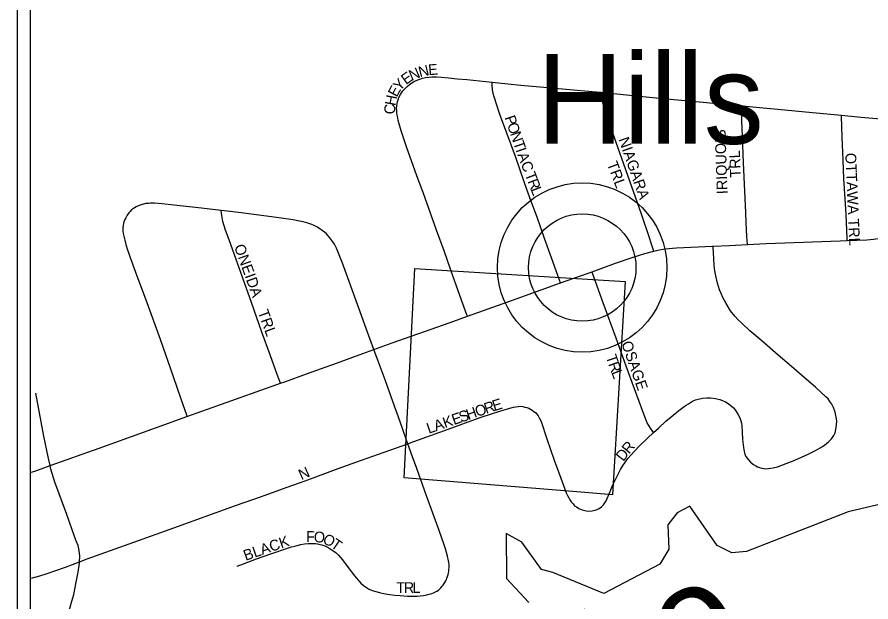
# Model space of a CAD drawing. Extents: x -5.4 to 49.9, y 13.2 to 48.4.
# Drawn here: x 26.266 to 27.015, y 43.012 to 43.526 of the extents above; entities that cross this region are included whole.
import ezdxf

# ---------------------------------------------------------------- set-up
doc = ezdxf.new("R2010")
doc.units = 0
for name, color, linetype in [('GM_X_Corporation', 7, 'Continuous'), ('GM_X_Major_Lake', 7, 'Continuous'), ('GM_X_Major_Lake_Text', 7, 'Continuous'), ('GM_X_Township', 7, 'Continuous'), ('GM_X_Township_Road', 7, 'Continuous'), ('GM_X_Township_Subdivision', 7, 'Continuous'), ('GM_X_Township_Subdivision_Text', 7, 'Continuous'), ('GM_X_Unincorporated', 7, 'Continuous'), ('GM_X_Unincorporated_Location', 7, 'Continuous'), ('GM_X_Unincorporated_Text', 7, 'Continuous')]:
    doc.layers.add(name, color=color, linetype=linetype)

msp = doc.modelspace()

# ---------------------------------------------------------------- linework, layer by layer
at = {"layer": 'GM_X_Corporation'}
msp.add_line((26.26551, 43.78252), (26.26551, 42.05419), dxfattribs=at)
msp.add_lwpolyline([(26.61474, 43.30541), (26.79932, 43.29416), (26.78844, 43.10649), (26.75689, 43.10905), (26.60546, 43.12136), (26.61474, 43.30541)], dxfattribs=at)
at = {"layer": 'GM_X_Major_Lake'}
msp.add_lwpolyline([(27.05104, 43.10483), (26.9954, 43.09164), (26.90591, 43.0568), (26.89299, 43.05556), (26.88025, 43.06191), (26.87364, 43.07155), (26.85638, 43.09659), (26.84525, 43.09076), (26.83706, 43.08032), (26.83771, 43.05868), (26.82984, 43.04557), (26.78074, 43.01971), (26.73603, 43.03815), (26.72586, 43.04103), (26.70858, 43.06493), (26.6951, 43.07244), (26.69535, 43.03297), (26.71498, 43.01205)], dxfattribs=at)
at = {"layer": 'GM_X_Township'}
msp.add_line((26.2771, 45.17828), (26.2771, 40.9761), dxfattribs=at)
at = {"layer": 'GM_X_Township_Road'}
for points in [[(26.90688, 43.32649), (26.92316, 43.32728), (26.94794, 43.32823), (26.98827, 43.32971), (26.99436, 43.32999)], [(26.99436, 43.32999), (27.0118, 43.33078), (27.01744, 43.33118), (27.02367, 43.33221), (27.02492, 43.33258)], [(26.77037, 43.30264), (26.79093, 43.31011), (26.80559, 43.31511), (26.81682, 43.31861), (26.82461, 43.3206)], [(26.82461, 43.3206), (26.82817, 43.3215), (26.83421, 43.3226), (26.84465, 43.32372), (26.87611, 43.32497), (26.87679, 43.325)], [(26.87679, 43.325), (26.89096, 43.32572), (26.90688, 43.32649)], [(26.74281, 43.29278), (26.76702, 43.30142), (26.77037, 43.30264)], [(26.66104, 43.26349), (26.67499, 43.26842), (26.70063, 43.27772), (26.72559, 43.28663), (26.74281, 43.29278)], [(26.5789, 43.23416), (26.59494, 43.23999), (26.64576, 43.25809), (26.66104, 43.26349)], [(26.4967, 43.20464), (26.50049, 43.206), (26.51966, 43.21291), (26.5461, 43.22233), (26.56925, 43.23065), (26.5789, 43.23416)], [(26.41468, 43.17539), (26.44106, 43.18478), (26.4967, 43.20464)], [(26.29447, 43.13221), (26.33759, 43.14753), (26.37642, 43.16151), (26.39434, 43.16814), (26.41468, 43.17539)], [(26.2771, 43.12614), (26.28109, 43.12745), (26.29447, 43.13221)]]:
    msp.add_lwpolyline(points, dxfattribs=at)
at = {"layer": 'GM_X_Township_Subdivision'}
for points in [[(26.66104, 43.26349), (26.66056, 43.26475), (26.65699, 43.27429), (26.65416, 43.28183), (26.64644, 43.3041), (26.6406, 43.32084), (26.63374, 43.33919), (26.62207, 43.37233), (26.61665, 43.38698), (26.60746, 43.41229), (26.60273, 43.4263), (26.60088, 43.43253), (26.60015, 43.43548), (26.5997, 43.43787), (26.59929, 43.44028), (26.59897, 43.44253), (26.5989, 43.4443), (26.59876, 43.44648), (26.59894, 43.44852), (26.59925, 43.4503), (26.59963, 43.45213), (26.60011, 43.45369), (26.60084, 43.45561), (26.6022, 43.45839), (26.60313, 43.45992), (26.60431, 43.46145), (26.60621, 43.46362), (26.60814, 43.46547), (26.6101, 43.46713), (26.61207, 43.46848), (26.61355, 43.46941), (26.61525, 43.47037), (26.61731, 43.47127), (26.61919, 43.47197), (26.62155, 43.47266), (26.62422, 43.4733), (26.62705, 43.47367), (26.62958, 43.47379), (26.63139, 43.47387), (26.63386, 43.47386), (26.63816, 43.47359), (26.6443, 43.47302), (26.65188, 43.47228), (26.66033, 43.47144), (26.68276, 43.46918)], [(26.68276, 43.46918), (26.69649, 43.46779), (26.70793, 43.46671), (26.73125, 43.46466), (26.75084, 43.4629), (26.7706, 43.46113), (26.7783, 43.46036)], [(26.74281, 43.29278), (26.74191, 43.29523), (26.73469, 43.31489), (26.72868, 43.33183), (26.7223, 43.35056), (26.71561, 43.36765), (26.7111, 43.3808), (26.70325, 43.40375), (26.69564, 43.42428), (26.68922, 43.44155), (26.68446, 43.45645), (26.68394, 43.45816), (26.68353, 43.45967), (26.6832, 43.46115), (26.683, 43.46247), (26.68283, 43.46378), (26.68281, 43.46572), (26.68276, 43.46918)], [(26.7783, 43.46036), (26.78923, 43.45927), (26.82087, 43.45612), (26.84215, 43.454), (26.86793, 43.45157), (26.89395, 43.44911), (26.90269, 43.44835)], [(26.82461, 43.3206), (26.82265, 43.32677), (26.82059, 43.3333), (26.81367, 43.35329), (26.79992, 43.39217), (26.79152, 43.41633), (26.78388, 43.43829), (26.78082, 43.44762), (26.77982, 43.45138), (26.77884, 43.4554), (26.77848, 43.45843), (26.7783, 43.46036)], [(26.90688, 43.32649), (26.90643, 43.33365), (26.90583, 43.3459), (26.9054, 43.35472), (26.90347, 43.39839), (26.90243, 43.4218), (26.90182, 43.43528), (26.90193, 43.44031), (26.90213, 43.44354), (26.90239, 43.44639), (26.90269, 43.44835)], [(26.90269, 43.44835), (26.91746, 43.44706), (26.93349, 43.44541), (26.96381, 43.44258), (26.98934, 43.44019)], [(26.98934, 43.44019), (27.00649, 43.43859), (27.03764, 43.43588), (27.06877, 43.43298), (27.07594, 43.43232), (27.08162, 43.43152), (27.08606, 43.43062), (27.08894, 43.42996), (27.09214, 43.42897), (27.09502, 43.42774), (27.09749, 43.42651), (27.10003, 43.42519), (27.10283, 43.42346), (27.10764, 43.41985), (27.1164, 43.41327), (27.13392, 43.39922)], [(26.99436, 43.32999), (26.99429, 43.33171), (26.99344, 43.35317), (26.99154, 43.38454), (26.99073, 43.40067), (26.99001, 43.42075), (26.98936, 43.43899), (26.98934, 43.44019)], [(26.44479, 43.35632), (26.42746, 43.35835), (26.40868, 43.36064), (26.39812, 43.36176), (26.39254, 43.36235), (26.3895, 43.36259), (26.38605, 43.36277), (26.38275, 43.36287), (26.38087, 43.36267), (26.37852, 43.36246), (26.37541, 43.36176), (26.37281, 43.36094), (26.36994, 43.35962), (26.3678, 43.35831), (26.36607, 43.35708), (26.36467, 43.35568), (26.36361, 43.35437), (26.36213, 43.35231), (26.3609, 43.35007), (26.36016, 43.34853), (26.35938, 43.34649), (26.359, 43.34489), (26.35863, 43.34333), (26.35835, 43.34187), (26.35827, 43.34039), (26.35835, 43.33842), (26.35868, 43.33612), (26.35917, 43.33381), (26.35999, 43.33044), (26.36106, 43.32656), (26.36252, 43.32175), (26.36352, 43.31869), (26.36482, 43.31525), (26.36948, 43.3023), (26.37935, 43.27567), (26.39105, 43.24332), (26.40253, 43.21045), (26.40933, 43.19095), (26.41425, 43.17676), (26.41468, 43.17539)], [(26.5789, 43.23416), (26.57562, 43.24299), (26.57089, 43.25602), (26.56562, 43.27059), (26.56106, 43.28337), (26.55483, 43.30056), (26.55118, 43.31019), (26.54782, 43.31894), (26.54585, 43.32337), (26.54413, 43.32675), (26.5419, 43.33012), (26.53999, 43.33248), (26.53853, 43.33422), (26.53714, 43.33579), (26.53541, 43.33727), (26.53338, 43.33898), (26.53179, 43.34014), (26.52923, 43.34178), (26.52686, 43.34294), (26.52421, 43.34421), (26.52094, 43.34533), (26.51684, 43.3464), (26.51215, 43.34738), (26.5078, 43.3482), (26.4954, 43.3501), (26.48009, 43.35215), (26.46239, 43.35439), (26.44997, 43.35572), (26.44479, 43.35632)], [(26.4967, 43.20464), (26.49402, 43.21236), (26.48779, 43.22945), (26.48049, 43.24951), (26.47126, 43.27561), (26.46232, 43.30094), (26.45161, 43.33076), (26.44863, 43.33904), (26.44608, 43.34674), (26.44522, 43.35217), (26.44479, 43.35632)], [(26.82439, 43.1613), (26.82862, 43.16521), (26.83509, 43.17124), (26.83979, 43.1752), (26.84333, 43.17817), (26.84777, 43.18154), (26.8512, 43.18415), (26.85302, 43.18529), (26.85515, 43.18661), (26.85674, 43.18767), (26.85859, 43.18875), (26.86114, 43.18998), (26.86345, 43.19064), (26.86739, 43.19154), (26.87109, 43.19187), (26.8743, 43.19187), (26.8789, 43.19113), (26.88244, 43.19024), (26.88498, 43.18933), (26.88741, 43.18818), (26.88901, 43.18727), (26.89097, 43.18608), (26.89229, 43.18497), (26.89446, 43.18295), (26.896, 43.18119), (26.89698, 43.17987), (26.89845, 43.17732), (26.90013, 43.1742), (26.90109, 43.17144), (26.90159, 43.16952), (26.90181, 43.1673), (26.90225, 43.16178), (26.90262, 43.15508), (26.9034, 43.14822), (26.90397, 43.14461), (26.90463, 43.14231), (26.90553, 43.14033), (26.90652, 43.13885), (26.90767, 43.13745), (26.90965, 43.13524), (26.91203, 43.13333), (26.91416, 43.13195), (26.91556, 43.13121), (26.91745, 43.13055), (26.91943, 43.13006), (26.92296, 43.12948), (26.92534, 43.12956), (26.92946, 43.13014), (26.93307, 43.13129), (26.94853, 43.13701), (26.9602, 43.14239), (26.96663, 43.14563), (26.97055, 43.14773), (26.97442, 43.15028), (26.97812, 43.15307), (26.98058, 43.15578), (26.98272, 43.15858), (26.98371, 43.16113), (26.98453, 43.164), (26.98511, 43.16812), (26.98527, 43.17116), (26.98506, 43.17331), (26.98455, 43.1764), (26.98388, 43.1793), (26.98232, 43.18341), (26.9809, 43.18621), (26.97927, 43.18867), (26.97762, 43.1908), (26.9757, 43.19262), (26.96651, 43.20129), (26.9607, 43.20625), (26.94344, 43.22123), (26.93393, 43.22935), (26.91943, 43.24182), (26.909, 43.25061), (26.90179, 43.2573), (26.89877, 43.26039), (26.89586, 43.26355), (26.89208, 43.26833), (26.88805, 43.27457), (26.88536, 43.28001), (26.88373, 43.28344), (26.88242, 43.28675), (26.88054, 43.29257), (26.87904, 43.2991), (26.87806, 43.30355), (26.87767, 43.30816), (26.8772, 43.31417), (26.87683, 43.32414), (26.87679, 43.325)], [(26.82439, 43.1613), (26.82368, 43.16233), (26.82164, 43.16523), (26.82023, 43.1674), (26.81891, 43.16993), (26.81768, 43.17268), (26.81379, 43.18311), (26.80769, 43.19971), (26.80034, 43.21971), (26.79143, 43.24424), (26.78022, 43.27521), (26.77081, 43.3014), (26.77037, 43.30264)], [(26.60866, 43.15141), (26.60719, 43.15545), (26.60183, 43.17075), (26.59559, 43.18853), (26.58867, 43.20764), (26.58264, 43.22409), (26.5789, 43.23416)], [(26.29447, 43.13221), (26.29272, 43.13991), (26.28901, 43.15813), (26.28204, 43.19597)], [(26.60866, 43.15141), (26.6108, 43.15217), (26.64407, 43.16428), (26.67131, 43.17415), (26.68285, 43.17797), (26.69403, 43.18168), (26.7013, 43.18362), (26.70323, 43.18398), (26.70545, 43.18422), (26.70743, 43.18439), (26.70958, 43.18404), (26.71129, 43.18373), (26.71303, 43.18322), (26.71474, 43.18258), (26.71631, 43.18182), (26.71779, 43.18094), (26.71931, 43.17992), (26.72058, 43.17897), (26.72189, 43.17748), (26.72296, 43.17593), (26.72403, 43.17428), (26.72559, 43.17091), (26.73071, 43.15585), (26.73714, 43.13693), (26.74088, 43.12669), (26.74491, 43.11576), (26.74771, 43.10835), (26.74885, 43.10597), (26.75004, 43.10377), (26.75091, 43.10219), (26.75215, 43.10038), (26.75368, 43.09851), (26.75502, 43.09701), (26.75658, 43.09595), (26.75883, 43.0946), (26.76183, 43.09342), (26.76527, 43.09256), (26.76817, 43.09233), (26.77048, 43.09249), (26.77303, 43.09315), (26.77475, 43.09376), (26.77658, 43.09459), (26.77879, 43.0961), (26.78042, 43.09775), (26.78166, 43.09964), (26.78268, 43.10132), (26.78619, 43.10934), (26.78872, 43.11526), (26.79144, 43.12122), (26.79349, 43.12529), (26.7955, 43.12882), (26.79719, 43.13179), (26.79981, 43.13554), (26.80188, 43.13836), (26.80436, 43.14131), (26.80796, 43.14526), (26.8115, 43.14892), (26.81914, 43.15644), (26.82439, 43.1613)], [(26.32044, 43.0478), (26.32716, 43.05041), (26.36815, 43.06509), (26.40322, 43.07767), (26.45743, 43.09709), (26.48001, 43.1052), (26.50179, 43.11286), (26.51847, 43.11881), (26.54756, 43.12959), (26.56786, 43.13695), (26.59272, 43.14576), (26.60866, 43.15141)], [(26.45876, 43.04383), (26.4644, 43.04594), (26.47581, 43.05026), (26.48846, 43.05464), (26.50397, 43.06), (26.5066, 43.06082), (26.50915, 43.06156), (26.51137, 43.06206), (26.51465, 43.0628), (26.51778, 43.06337), (26.52107, 43.06386), (26.52378, 43.06386), (26.52583, 43.06386), (26.52756, 43.0637), (26.52937, 43.06345), (26.53151, 43.06304), (26.53323, 43.06255), (26.5357, 43.06165), (26.53738, 43.06082), (26.54004, 43.05941), (26.54227, 43.05803), (26.54454, 43.05636), (26.54589, 43.05523), (26.5477, 43.05356), (26.5513, 43.04941), (26.55972, 43.0379), (26.56325, 43.03354), (26.5652, 43.03139), (26.56748, 43.02887), (26.56948, 43.02712), (26.57145, 43.02566), (26.57418, 43.02404), (26.57729, 43.0226), (26.58061, 43.02147), (26.58371, 43.02062), (26.58618, 43.02003), (26.58913, 43.01947), (26.59287, 43.01898), (26.59717, 43.01841), (26.60181, 43.018), (26.60828, 43.01759), (26.6141, 43.01742), (26.61681, 43.01745), (26.61973, 43.01771), (26.62244, 43.01808), (26.62421, 43.01841), (26.62604, 43.0189), (26.62743, 43.01923), (26.62957, 43.01988), (26.6312, 43.02051), (26.63288, 43.02133), (26.63422, 43.02203), (26.63547, 43.02285), (26.63666, 43.02383), (26.63765, 43.02477), (26.63876, 43.02614), (26.63952, 43.02709), (26.64049, 43.02848), (26.64118, 43.02962), (26.64188, 43.03086), (26.64253, 43.03226), (26.64299, 43.03345), (26.64349, 43.03469), (26.64406, 43.03661), (26.64435, 43.03789), (26.64453, 43.03918), (26.64472, 43.04085), (26.64491, 43.04274), (26.64495, 43.0452), (26.64471, 43.04712), (26.64443, 43.04849), (26.64358, 43.05264), (26.64176, 43.05917), (26.64062, 43.06268), (26.63609, 43.07525), (26.63182, 43.08711), (26.62503, 43.10573), (26.61655, 43.12974), (26.6128, 43.13998), (26.60866, 43.15141)], [(26.32044, 43.0478), (26.32066, 43.0527), (26.32013, 43.05756), (26.31904, 43.06192), (26.31718, 43.06679), (26.31599, 43.06988), (26.30908, 43.08912), (26.29876, 43.1178), (26.29519, 43.12903), (26.29447, 43.13221)], [(26.2771, 43.03328), (26.27905, 43.03374), (26.28557, 43.03544), (26.29106, 43.03712), (26.30812, 43.04302), (26.32044, 43.0478)], [(26.2771, 42.97921), (26.28218, 42.97904), (26.28775, 42.97953), (26.29143, 42.98024), (26.29461, 42.98155), (26.29686, 42.98296), (26.29939, 42.98474), (26.30262, 42.9877), (26.30495, 42.99061), (26.30681, 42.99381), (26.30802, 42.99655), (26.30943, 43.00012), (26.31204, 43.00779), (26.31363, 43.01314), (26.31522, 43.0191), (26.31741, 43.02987), (26.31917, 43.03853), (26.32038, 43.04651), (26.32044, 43.0478)]]:
    msp.add_lwpolyline(points, dxfattribs=at)
at = {"layer": 'GM_X_Unincorporated'}
for radius in [0.0744, 0.04716]:
    msp.add_circle((26.76176, 43.30631), radius, dxfattribs=at)
at = {"layer": 'GM_X_Unincorporated_Location'}
msp.add_line((26.76176, 43.30631), (26.76176, 43.30631), dxfattribs=at)

# ---------------------------------------------------------------- texts
at = {"layer": 'GM_X_Major_Lake_Text'}
msp.add_text('Lake', height=0.094691, rotation=28.51356, dxfattribs=at).set_placement((26.67048, 42.84241))
at = {"layer": 'GM_X_Township_Subdivision_Text'}
for s, rotation, p in [('N', 13.61219, (26.61919, 43.47335)), ('E', 4.86799, (26.62692, 43.47525)), ('E', 35.60755, (26.60699, 43.46658)), ('N', 23.27895, (26.61194, 43.47019)), ('Y', 47.21032, (26.60171, 43.46079)), ('E', 61.77324, (26.59892, 43.45544)), ('H', 78.78008, (26.59755, 43.44796)), ('C', 89.07712, (26.59748, 43.44091)), ('P', 288.86704, (26.69345, 43.43819)), ('O', 288.87612, (26.6956, 43.43188)), ('N', 288.87612, (26.6983, 43.424)), ('IRIQUOIS', 91.90819, (26.88939, 43.37092)), ('T', 288.87073, (26.70099, 43.41611)), ('NIAGARA', 289.28957, (26.79344, 43.41904)), ('I', 289.15462, (26.70316, 43.40976)), ('A', 290.45874, (26.70461, 43.4056)), ('TRL', 92.20132, (26.90108, 43.38557)), ('OTTAWA TRL', 272.54735, (26.9927, 43.40683)), ('C', 291.10355, (26.70756, 43.39769)), ('TRL', 290.55505, (26.78334, 43.39758)), ('T', 291.10619, (26.71117, 43.38835)), ('R', 291.14108, (26.71357, 43.38213)), ('L', 291.10619, (26.71627, 43.37513)), ('ONEIDA', 289.79501, (26.45594, 43.32487)), ('TRL', 289.80322, (26.47677, 43.26738)), ('OSAGE', 289.23025, (26.79594, 43.23987)), ('T', 288.5127, (26.78233, 43.22808)), ('R', 289.40167, (26.7845, 43.22161)), ('L', 291.08236, (26.78709, 43.21425)), ('O', 19.18973, (26.6695, 43.17493)), ('R', 18.4119, (26.67733, 43.17766)), ('E', 17.28555, (26.6844, 43.18001)), ('E', 19.19559, (26.64904, 43.1678)), ('S', 19.20368, (26.65533, 43.17)), ('H', 19.19516, (26.66163, 43.17219)), ('L', 19.21267, (26.627, 43.16013)), ('A', 19.19516, (26.6333, 43.16232)), ('K', 19.18973, (26.64117, 43.16506)), ('R', 50.07314, (26.80282, 43.14186)), ('D', 52.54868, (26.79782, 43.13533)), ('N', 23.96474, (26.5152, 43.11924)), ('F', 359.18037, (26.51922, 43.06523)), ('O', 355.00943, (26.52571, 43.06515)), ('BLACK', 19.17458, (26.46618, 43.04847)), ('O', 332.68226, (26.53308, 43.06469)), ('T', 325.50695, (26.54021, 43.06103)), ('T', 0.16394, (26.59843, 43.02023)), ('R', 0.16083, (26.6051, 43.02025)), ('L', 0.15955, (26.6126, 43.02027))]:
    msp.add_text(s, height=0.00947, rotation=rotation, dxfattribs=at).set_placement(p)
at = {"layer": 'GM_X_Unincorporated_Text'}
msp.add_text('Hills', height=0.078977, rotation=0.00001, dxfattribs=at).set_placement((26.72176, 43.41507))

doc.saveas('drawing.dxf')
